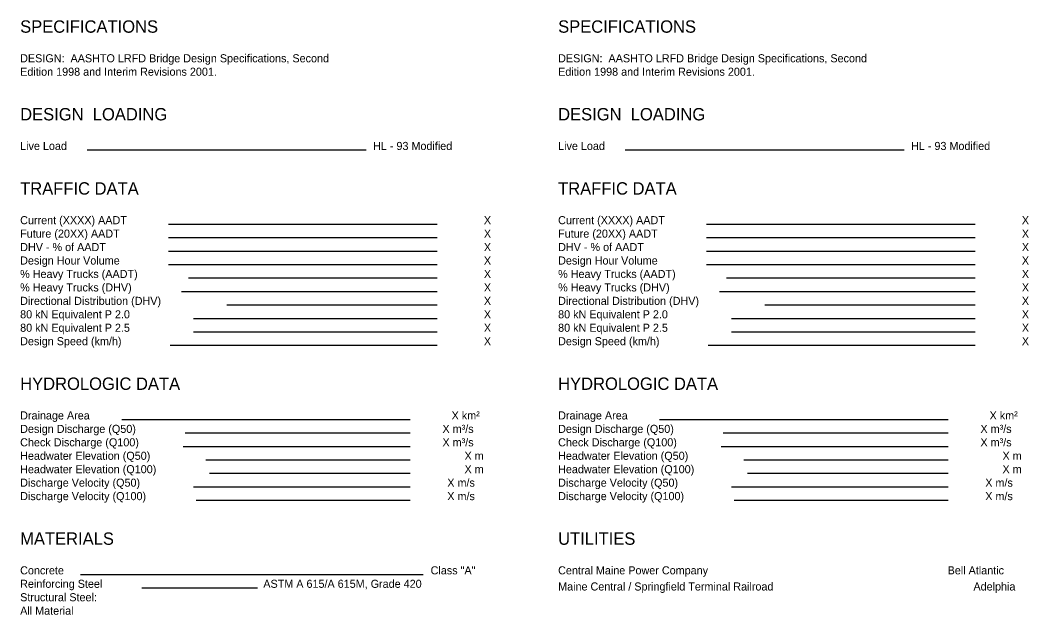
# Model space of a CAD drawing. Extents: x 605371.3 to 605398.1, y 420183.2 to 420214.1.
# Drawn here: x 605390.579 to 605390.954, y 420198.9946 to 420199.2157 of the extents above; entities that cross this region are included whole.
import ezdxf

# ---------------------------------------------------------------- set-up
doc = ezdxf.new("R2010")
doc.units = 0
doc.layers.add('Fram_Steel', color=7, linetype='Continuous')

msp = doc.modelspace()

# ---------------------------------------------------------------- linework, layer by layer
at = {"layer": 'Fram_Steel'}
for p, q in [((605390.60395, 420199.1674), (605390.70762, 420199.1674)), ((605390.60395, 420199.1674), (605390.70762, 420199.1674)), ((605390.80395, 420199.1674), (605390.90762, 420199.1674)), ((605390.80395, 420199.1674), (605390.90762, 420199.1674)), ((605390.63412, 420199.1398), (605390.734, 420199.1398)), ((605390.63412, 420199.1398), (605390.734, 420199.1398)), ((605390.83412, 420199.1398), (605390.934, 420199.1398)), ((605390.83412, 420199.1398), (605390.934, 420199.1398)), ((605390.63412, 420199.1348), (605390.734, 420199.1348)), ((605390.63412, 420199.1348), (605390.734, 420199.1348)), ((605390.83412, 420199.1348), (605390.934, 420199.1348)), ((605390.83412, 420199.1348), (605390.934, 420199.1348)), ((605390.63412, 420199.1298), (605390.734, 420199.1298)), ((605390.63412, 420199.1298), (605390.734, 420199.1298)), ((605390.83412, 420199.1298), (605390.934, 420199.1298)), ((605390.83412, 420199.1298), (605390.934, 420199.1298)), ((605390.63412, 420199.1248), (605390.734, 420199.1248)), ((605390.63412, 420199.1248), (605390.734, 420199.1248)), ((605390.83412, 420199.1248), (605390.934, 420199.1248)), ((605390.83412, 420199.1248), (605390.934, 420199.1248)), ((605390.64157, 420199.1198), (605390.734, 420199.1198)), ((605390.64157, 420199.1198), (605390.734, 420199.1198)), ((605390.84157, 420199.1198), (605390.934, 420199.1198)), ((605390.84157, 420199.1198), (605390.934, 420199.1198)), ((605390.63895, 420199.1148), (605390.734, 420199.1148)), ((605390.63895, 420199.1148), (605390.734, 420199.1148)), ((605390.83895, 420199.1148), (605390.934, 420199.1148)), ((605390.83895, 420199.1148), (605390.934, 420199.1148)), ((605390.65585, 420199.1098), (605390.734, 420199.1098)), ((605390.65585, 420199.1098), (605390.734, 420199.1098)), ((605390.85585, 420199.1098), (605390.934, 420199.1098)), ((605390.85585, 420199.1098), (605390.934, 420199.1098)), ((605390.64341, 420199.1048), (605390.734, 420199.1048)), ((605390.64341, 420199.1048), (605390.734, 420199.1048)), ((605390.84341, 420199.1048), (605390.934, 420199.1048)), ((605390.84341, 420199.1048), (605390.934, 420199.1048)), ((605390.64341, 420199.0998), (605390.734, 420199.0998)), ((605390.64341, 420199.0998), (605390.734, 420199.0998)), ((605390.84341, 420199.0998), (605390.934, 420199.0998)), ((605390.84341, 420199.0998), (605390.934, 420199.0998)), ((605390.63481, 420199.0948), (605390.734, 420199.0948)), ((605390.63481, 420199.0948), (605390.734, 420199.0948)), ((605390.83481, 420199.0948), (605390.934, 420199.0948)), ((605390.83481, 420199.0948), (605390.934, 420199.0948)), ((605390.61674, 420199.0672), (605390.724, 420199.0672)), ((605390.61674, 420199.0672), (605390.724, 420199.0672)), ((605390.81674, 420199.0672), (605390.924, 420199.0672)), ((605390.81674, 420199.0672), (605390.924, 420199.0672)), ((605390.64035, 420199.0622), (605390.724, 420199.0622)), ((605390.64035, 420199.0622), (605390.724, 420199.0622)), ((605390.84035, 420199.0622), (605390.924, 420199.0622)), ((605390.84035, 420199.0622), (605390.924, 420199.0622)), ((605390.6396, 420199.0572), (605390.724, 420199.0572)), ((605390.6396, 420199.0572), (605390.724, 420199.0572)), ((605390.8396, 420199.0572), (605390.924, 420199.0572)), ((605390.8396, 420199.0572), (605390.924, 420199.0572)), ((605390.64802, 420199.0522), (605390.724, 420199.0522)), ((605390.64802, 420199.0522), (605390.724, 420199.0522)), ((605390.84802, 420199.0522), (605390.924, 420199.0522)), ((605390.84802, 420199.0522), (605390.924, 420199.0522)), ((605390.64936, 420199.0472), (605390.724, 420199.0472)), ((605390.64936, 420199.0472), (605390.724, 420199.0472)), ((605390.84936, 420199.0472), (605390.924, 420199.0472)), ((605390.84936, 420199.0472), (605390.924, 420199.0472)), ((605390.64348, 420199.0422), (605390.724, 420199.0422)), ((605390.64348, 420199.0422), (605390.724, 420199.0422)), ((605390.84348, 420199.0422), (605390.924, 420199.0422)), ((605390.84348, 420199.0422), (605390.924, 420199.0422)), ((605390.64445, 420199.0372), (605390.724, 420199.0372)), ((605390.64445, 420199.0372), (605390.724, 420199.0372)), ((605390.84445, 420199.0372), (605390.924, 420199.0372)), ((605390.84445, 420199.0372), (605390.924, 420199.0372)), ((605390.60146, 420199.0096), (605390.72885, 420199.0096)), ((605390.60146, 420199.0096), (605390.72885, 420199.0096)), ((605390.62423, 420199.0046), (605390.66729, 420199.0046)), ((605390.62423, 420199.0046), (605390.66729, 420199.0046))]:
    msp.add_line(p, q, dxfattribs=at)

# ---------------------------------------------------------------- texts
for s, height, p in [('SPECIFICATIONS', 0.0045996, (605390.579, 420199.211)), ('SPECIFICATIONS', 0.0045996, (605390.579, 420199.211)), ('SPECIFICATIONS', 0.0045996, (605390.779, 420199.211)), ('SPECIFICATIONS', 0.0045996, (605390.779, 420199.211)), ('DESIGN:  AASHTO LRFD Bridge Design Specifications, Second', 0.003, (605390.579, 420199.2)), ('DESIGN:  AASHTO LRFD Bridge Design Specifications, Second', 0.003, (605390.579, 420199.2)), ('DESIGN:  AASHTO LRFD Bridge Design Specifications, Second', 0.003, (605390.779, 420199.2)), ('DESIGN:  AASHTO LRFD Bridge Design Specifications, Second', 0.003, (605390.779, 420199.2)), ('Edition 1998 and Interim Revisions 2001.', 0.003, (605390.579, 420199.195)), ('Edition 1998 and Interim Revisions 2001.', 0.003, (605390.579, 420199.195)), ('Edition 1998 and Interim Revisions 2001.', 0.003, (605390.779, 420199.195)), ('Edition 1998 and Interim Revisions 2001.', 0.003, (605390.779, 420199.195)), ('DESIGN  LOADING', 0.0045996, (605390.579, 420199.1784)), ('DESIGN  LOADING', 0.0045996, (605390.579, 420199.1784)), ('DESIGN  LOADING', 0.0045996, (605390.779, 420199.1784)), ('DESIGN  LOADING', 0.0045996, (605390.779, 420199.1784)), ('Live Load', 0.003, (605390.579, 420199.1674)), ('Live Load', 0.003, (605390.579, 420199.1674)), ('HL - 93 Modified', 0.003, (605390.7102, 420199.1674)), ('HL - 93 Modified', 0.003, (605390.7102, 420199.1674)), ('Live Load', 0.003, (605390.779, 420199.1674)), ('Live Load', 0.003, (605390.779, 420199.1674)), ('HL - 93 Modified', 0.003, (605390.9102, 420199.1674)), ('HL - 93 Modified', 0.003, (605390.9102, 420199.1674)), ('TRAFFIC DATA', 0.0045996, (605390.579, 420199.1508)), ('TRAFFIC DATA', 0.0045996, (605390.579, 420199.1508)), ('TRAFFIC DATA', 0.0045996, (605390.779, 420199.1508)), ('TRAFFIC DATA', 0.0045996, (605390.779, 420199.1508)), ('Current (XXXX) AADT', 0.003, (605390.579, 420199.1398)), ('Current (XXXX) AADT', 0.003, (605390.579, 420199.1398)), ('X', 0.003, (605390.7514, 420199.1398)), ('X', 0.003, (605390.7514, 420199.1398)), ('Current (XXXX) AADT', 0.003, (605390.779, 420199.1398)), ('Current (XXXX) AADT', 0.003, (605390.779, 420199.1398)), ('X', 0.003, (605390.9514, 420199.1398)), ('X', 0.003, (605390.9514, 420199.1398)), ('Future (20XX) AADT', 0.003, (605390.579, 420199.1348)), ('Future (20XX) AADT', 0.003, (605390.579, 420199.1348)), ('X', 0.003, (605390.7514, 420199.1348)), ('X', 0.003, (605390.7514, 420199.1348)), ('Future (20XX) AADT', 0.003, (605390.779, 420199.1348)), ('Future (20XX) AADT', 0.003, (605390.779, 420199.1348)), ('X', 0.003, (605390.9514, 420199.1348)), ('X', 0.003, (605390.9514, 420199.1348)), ('DHV - % of AADT', 0.003, (605390.579, 420199.1298)), ('DHV - % of AADT', 0.003, (605390.579, 420199.1298)), ('X', 0.003, (605390.7514, 420199.1298)), ('X', 0.003, (605390.7514, 420199.1298)), ('DHV - % of AADT', 0.003, (605390.779, 420199.1298)), ('DHV - % of AADT', 0.003, (605390.779, 420199.1298)), ('X', 0.003, (605390.9514, 420199.1298)), ('X', 0.003, (605390.9514, 420199.1298)), ('Design Hour Volume', 0.003, (605390.579, 420199.1248)), ('Design Hour Volume', 0.003, (605390.579, 420199.1248)), ('X', 0.003, (605390.7514, 420199.1248)), ('X', 0.003, (605390.7514, 420199.1248)), ('Design Hour Volume', 0.003, (605390.779, 420199.1248)), ('Design Hour Volume', 0.003, (605390.779, 420199.1248)), ('X', 0.003, (605390.9514, 420199.1248)), ('X', 0.003, (605390.9514, 420199.1248)), ('% Heavy Trucks (AADT)', 0.003, (605390.579, 420199.1198)), ('% Heavy Trucks (AADT)', 0.003, (605390.579, 420199.1198)), ('X', 0.003, (605390.7514, 420199.1198)), ('X', 0.003, (605390.7514, 420199.1198)), ('% Heavy Trucks (AADT)', 0.003, (605390.779, 420199.1198)), ('% Heavy Trucks (AADT)', 0.003, (605390.779, 420199.1198)), ('X', 0.003, (605390.9514, 420199.1198)), ('X', 0.003, (605390.9514, 420199.1198)), ('% Heavy Trucks (DHV)', 0.003, (605390.579, 420199.1148)), ('% Heavy Trucks (DHV)', 0.003, (605390.579, 420199.1148)), ('X', 0.003, (605390.7514, 420199.1148)), ('X', 0.003, (605390.7514, 420199.1148)), ('% Heavy Trucks (DHV)', 0.003, (605390.779, 420199.1148)), ('% Heavy Trucks (DHV)', 0.003, (605390.779, 420199.1148)), ('X', 0.003, (605390.9514, 420199.1148)), ('X', 0.003, (605390.9514, 420199.1148)), ('Directional Distribution (DHV)', 0.003, (605390.579, 420199.1098)), ('Directional Distribution (DHV)', 0.003, (605390.579, 420199.1098)), ('X', 0.003, (605390.7514, 420199.1098)), ('X', 0.003, (605390.7514, 420199.1098)), ('Directional Distribution (DHV)', 0.003, (605390.779, 420199.1098)), ('Directional Distribution (DHV)', 0.003, (605390.779, 420199.1098)), ('X', 0.003, (605390.9514, 420199.1098)), ('X', 0.003, (605390.9514, 420199.1098)), ('80 kN Equivalent P 2.0', 0.003, (605390.579, 420199.1048)), ('80 kN Equivalent P 2.0', 0.003, (605390.579, 420199.1048)), ('X', 0.003, (605390.7514, 420199.1048)), ('X', 0.003, (605390.7514, 420199.1048)), ('80 kN Equivalent P 2.0', 0.003, (605390.779, 420199.1048)), ('80 kN Equivalent P 2.0', 0.003, (605390.779, 420199.1048)), ('X', 0.003, (605390.9514, 420199.1048)), ('X', 0.003, (605390.9514, 420199.1048)), ('80 kN Equivalent P 2.5', 0.003, (605390.579, 420199.0998)), ('80 kN Equivalent P 2.5', 0.003, (605390.579, 420199.0998)), ('X', 0.003, (605390.7514, 420199.0998)), ('X', 0.003, (605390.7514, 420199.0998)), ('80 kN Equivalent P 2.5', 0.003, (605390.779, 420199.0998)), ('80 kN Equivalent P 2.5', 0.003, (605390.779, 420199.0998)), ('X', 0.003, (605390.9514, 420199.0998)), ('X', 0.003, (605390.9514, 420199.0998)), ('Design Speed (km/h)', 0.003, (605390.579, 420199.0948)), ('Design Speed (km/h)', 0.003, (605390.579, 420199.0948)), ('X', 0.003, (605390.7514, 420199.0948)), ('X', 0.003, (605390.7514, 420199.0948)), ('Design Speed (km/h)', 0.003, (605390.779, 420199.0948)), ('Design Speed (km/h)', 0.003, (605390.779, 420199.0948)), ('X', 0.003, (605390.9514, 420199.0948)), ('X', 0.003, (605390.9514, 420199.0948)), ('HYDROLOGIC DATA', 0.0045996, (605390.579, 420199.0782)), ('HYDROLOGIC DATA', 0.0045996, (605390.579, 420199.0782)), ('HYDROLOGIC DATA', 0.0045996, (605390.779, 420199.0782)), ('HYDROLOGIC DATA', 0.0045996, (605390.779, 420199.0782)), ('Drainage Area', 0.003, (605390.579, 420199.0672)), ('Drainage Area', 0.003, (605390.579, 420199.0672)), ('X km²', 0.003, (605390.7394, 420199.0672)), ('X km²', 0.003, (605390.7394, 420199.0672)), ('Drainage Area', 0.003, (605390.779, 420199.0672)), ('Drainage Area', 0.003, (605390.779, 420199.0672)), ('X km²', 0.003, (605390.9394, 420199.0672)), ('X km²', 0.003, (605390.9394, 420199.0672)), ('Design Discharge (Q50)', 0.003, (605390.579, 420199.0622)), ('Design Discharge (Q50)', 0.003, (605390.579, 420199.0622)), ('X m³/s', 0.003, (605390.736, 420199.0622)), ('X m³/s', 0.003, (605390.736, 420199.0622)), ('Design Discharge (Q50)', 0.003, (605390.779, 420199.0622)), ('Design Discharge (Q50)', 0.003, (605390.779, 420199.0622)), ('X m³/s', 0.003, (605390.936, 420199.0622)), ('X m³/s', 0.003, (605390.936, 420199.0622)), ('Check Discharge (Q100)', 0.003, (605390.579, 420199.0572)), ('Check Discharge (Q100)', 0.003, (605390.579, 420199.0572)), ('X m³/s', 0.003, (605390.736, 420199.0572)), ('X m³/s', 0.003, (605390.736, 420199.0572)), ('Check Discharge (Q100)', 0.003, (605390.779, 420199.0572)), ('Check Discharge (Q100)', 0.003, (605390.779, 420199.0572)), ('X m³/s', 0.003, (605390.936, 420199.0572)), ('X m³/s', 0.003, (605390.936, 420199.0572)), ('Headwater Elevation (Q50)', 0.003, (605390.579, 420199.0522)), ('Headwater Elevation (Q50)', 0.003, (605390.579, 420199.0522)), ('X m', 0.003, (605390.7442, 420199.0522)), ('X m', 0.003, (605390.7442, 420199.0522)), ('Headwater Elevation (Q50)', 0.003, (605390.779, 420199.0522)), ('Headwater Elevation (Q50)', 0.003, (605390.779, 420199.0522)), ('X m', 0.003, (605390.9442, 420199.0522)), ('X m', 0.003, (605390.9442, 420199.0522)), ('Headwater Elevation (Q100)', 0.003, (605390.579, 420199.0472)), ('Headwater Elevation (Q100)', 0.003, (605390.579, 420199.0472)), ('X m', 0.003, (605390.7442, 420199.0472)), ('X m', 0.003, (605390.7442, 420199.0472)), ('Headwater Elevation (Q100)', 0.003, (605390.779, 420199.0472)), ('Headwater Elevation (Q100)', 0.003, (605390.779, 420199.0472)), ('X m', 0.003, (605390.9442, 420199.0472)), ('X m', 0.003, (605390.9442, 420199.0472)), ('Discharge Velocity (Q50)', 0.003, (605390.579, 420199.0422)), ('Discharge Velocity (Q50)', 0.003, (605390.579, 420199.0422)), ('X m/s', 0.003, (605390.7378, 420199.0422)), ('X m/s', 0.003, (605390.7378, 420199.0422)), ('Discharge Velocity (Q50)', 0.003, (605390.779, 420199.0422)), ('Discharge Velocity (Q50)', 0.003, (605390.779, 420199.0422)), ('X m/s', 0.003, (605390.9378, 420199.0422)), ('X m/s', 0.003, (605390.9378, 420199.0422)), ('Discharge Velocity (Q100)', 0.003, (605390.579, 420199.0372)), ('Discharge Velocity (Q100)', 0.003, (605390.579, 420199.0372)), ('X m/s', 0.003, (605390.7378, 420199.0372)), ('X m/s', 0.003, (605390.7378, 420199.0372)), ('Discharge Velocity (Q100)', 0.003, (605390.779, 420199.0372)), ('Discharge Velocity (Q100)', 0.003, (605390.779, 420199.0372)), ('X m/s', 0.003, (605390.9378, 420199.0372)), ('X m/s', 0.003, (605390.9378, 420199.0372)), ('MATERIALS', 0.0046, (605390.579, 420199.0206)), ('MATERIALS', 0.0046, (605390.579, 420199.0206)), ('UTILITIES', 0.0046, (605390.779, 420199.0206)), ('UTILITIES', 0.0046, (605390.779, 420199.0206)), ('Concrete', 0.003, (605390.579, 420199.0096)), ('Concrete', 0.003, (605390.579, 420199.0096)), ('Class "A"', 0.003, (605390.7316, 420199.0096)), ('Class "A"', 0.003, (605390.7316, 420199.0096)), ('Central Maine Power Company', 0.003, (605390.779, 420199.0096)), ('Central Maine Power Company', 0.003, (605390.779, 420199.0096)), ('Bell Atlantic', 0.003, (605390.9238, 420199.0096)), ('Bell Atlantic', 0.003, (605390.9238, 420199.0096)), ('Reinforcing Steel', 0.003, (605390.579, 420199.0046)), ('Reinforcing Steel', 0.003, (605390.579, 420199.0046)), ('ASTM A 615/A 615M, Grade 420', 0.003, (605390.6694, 420199.0046)), ('ASTM A 615/A 615M, Grade 420', 0.003, (605390.6694, 420199.0046)), ('Maine Central / Springfield Terminal Railroad', 0.003, (605390.779, 420199.0036)), ('Maine Central / Springfield Terminal Railroad', 0.003, (605390.779, 420199.0036)), ('Adelphia', 0.003, (605390.9334, 420199.0036)), ('Adelphia', 0.003, (605390.9334, 420199.0036)), ('Structural Steel:', 0.003, (605390.579, 420198.9996)), ('Structural Steel:', 0.003, (605390.579, 420198.9996)), ('All Material', 0.003, (605390.579, 420198.9946)), ('All Material', 0.003, (605390.579, 420198.9946))]:
    msp.add_text(s, height=height, dxfattribs=at).set_placement(p)

doc.saveas('drawing.dxf')
